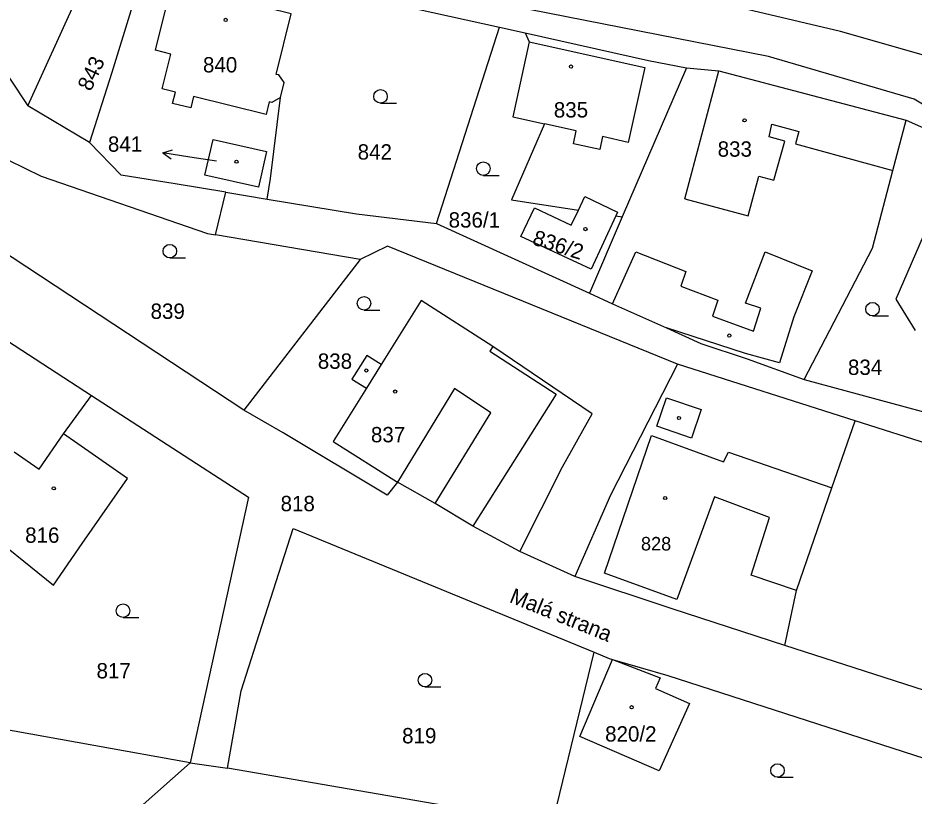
# Model space of a CAD drawing. Extents: x -504988 to -494607, y -1123820 to -1114018.
# Drawn here: x -497288.4 to -497189.2, y -1120348.7 to -1120262.5 of the extents above; entities that cross this region are included whole.
import ezdxf

# ---------------------------------------------------------------- set-up
doc = ezdxf.new("R2010")
doc.units = 0
for name, color, linetype in [('Hranice parcel', 7, 'Continuous'), ('Parcelní čísla', 7, 'Continuous'), ('Pop  PČ popisy', 7, 'Continuous'), ('Vnitřní kresba', 7, 'Continuous'), ('Značky budov', 7, 'Continuous'), ('Značky kultur', 7, 'Continuous')]:
    doc.layers.add(name, color=color, linetype=linetype)

msp = doc.modelspace()

# ---------------------------------------------------------------- linework, layer by layer
at = {"layer": 'Hranice parcel'}
for p, q in [((-497287.3, -1120272.28), (-497278.88, -1120253.77)), ((-497268.65, -1120256.06), (-497235.11, -1120263.57)), ((-497242.06, -1120285.3), (-497235.11, -1120263.57)), ((-497235.11, -1120263.57), (-497232.25, -1120264.21)), ((-497214.42, -1120268.07), (-497221.52, -1120284.58)), ((-497214.42, -1120268.07), (-497210.84, -1120268.41)), ((-497210.84, -1120268.41), (-497190.09, -1120273.86)), ((-497280.46, -1120276.35), (-497287.3, -1120272.28)), ((-497191.56, -1120279.46), (-497190.09, -1120273.86)), ((-497190.09, -1120273.86), (-497183.86, -1120276.68)), ((-497265.39, -1120281.85), (-497271, -1120280.93)), ((-497266.52, -1120286.57), (-497265.39, -1120281.85)), ((-497265.39, -1120281.85), (-497260.8, -1120282.61)), ((-497226.37, -1120283.83), (-497225.66, -1120282.33)), ((-497225.66, -1120282.33), (-497222.02, -1120284.08)), ((-497227.18, -1120285.52), (-497226.37, -1120283.83)), ((-497221.52, -1120284.58), (-497225.15, -1120293.04)), ((-497222.21, -1120284.47), (-497224.95, -1120290.36)), ((-497222.02, -1120284.08), (-497222.21, -1120284.47)), ((-497222.21, -1120284.47), (-497221.52, -1120284.58)), ((-497242.06, -1120285.3), (-497225.15, -1120293.04)), ((-497263.4, -1120305.99), (-497292.46, -1120286.83)), ((-497250.53, -1120289.32), (-497266.52, -1120286.57)), ((-497250.53, -1120289.32), (-497263.4, -1120305.99)), ((-497289.56, -1120298.33), (-497280.27, -1120304.35)), ((-497195.73, -1120307.17), (-497215.4, -1120300.88)), ((-497201.39, -1120302.61), (-497187.05, -1120306.47)), ((-497168.17, -1120315.99), (-497195.73, -1120307.17)), ((-497226.75, -1120324.4), (-497232.86, -1120321.63)), ((-497174.9, -1120341.31), (-497203.53, -1120332.06)), ((-497229.23, -1120351.83), (-497224.61, -1120332.8)), ((-497269.33, -1120345.06), (-497303.98, -1120338.81)), ((-497269.33, -1120345.06), (-497265.2, -1120345.62)), ((-497229.23, -1120351.83), (-497265.2, -1120345.62))]:
    msp.add_line(p, q, dxfattribs=at)
for points in [[(-497087.04, -1120354.48), (-497099.88, -1120329.46), (-497105.48, -1120320.32), (-497114.23, -1120310.57), (-497171.4, -1120273.63), (-497183.51, -1120268.01), (-497197.35, -1120264.04), (-497268.56, -1120247.23), (-497277.08, -1120243.87), (-497341.22, -1120209.24)], [(-497119.99, -1120315.01), (-497135.65, -1120304.45), (-497167.42, -1120284.15), (-497183.16, -1120275.2), (-497189.22, -1120271.56), (-497205.34, -1120266.82), (-497268.46, -1120254.4), (-497279.16, -1120250.56), (-497298.01, -1120244.32), (-497322.64, -1120230.85), (-497340.94, -1120216.65), (-497344.87, -1120214.42)], [(-497319.8, -1120246.25), (-497305.17, -1120245.35), (-497287.3, -1120272.28)], [(-497273.81, -1120254.9), (-497278.02, -1120268.58), (-497280.46, -1120276.35)], [(-497260.8, -1120282.61), (-497260.46, -1120280.35), (-497259.33, -1120271.37), (-497258.92, -1120269.72), (-497259.53, -1120268.87), (-497259.83, -1120268.8), (-497258.16, -1120262.08), (-497266.08, -1120260.12), (-497266.19, -1120260.59), (-497269.85, -1120259.82), (-497268.95, -1120256.58), (-497268.65, -1120256.06)], [(-497232.25, -1120264.21), (-497231.8, -1120265.2), (-497233.64, -1120273.5), (-497230.13, -1120274.28), (-497233.77, -1120282.69), (-497226.37, -1120283.83)], [(-497232.25, -1120264.21), (-497218.59, -1120267.27), (-497214.42, -1120268.07)], [(-497271, -1120280.93), (-497276.97, -1120279.95), (-497280.46, -1120276.35)], [(-497260.87, -1120277.35), (-497261.77, -1120281.31), (-497267.7, -1120279.97), (-497266.8, -1120276.01), (-497260.87, -1120277.35)], [(-497183.86, -1120276.68), (-497191.22, -1120293.71), (-497189.11, -1120297.17)], [(-497289.43, -1120278.3), (-497285.81, -1120280.06), (-497267.4, -1120286.42), (-497266.52, -1120286.57)], [(-497201.39, -1120302.61), (-497193.82, -1120288.05), (-497191.56, -1120279.46)], [(-497260.8, -1120282.61), (-497250.93, -1120284.24), (-497242.06, -1120285.3)], [(-497224.95, -1120290.36), (-497232.74, -1120286.74), (-497231.24, -1120283.59), (-497227.18, -1120285.52)], [(-497215.4, -1120300.88), (-497247.49, -1120287.81), (-497250.53, -1120289.32)], [(-497225.15, -1120293.04), (-497222.58, -1120294.2), (-497216.63, -1120296.87), (-497212.8, -1120298.59), (-497207.68, -1120300.3), (-497201.39, -1120302.61)], [(-497232.86, -1120321.63), (-497228.14, -1120312.28), (-497224.83, -1120306.41), (-497235.84, -1120298.93), (-497243.75, -1120293.83), (-497248.18, -1120300.93), (-497249.79, -1120299.93), (-497251.45, -1120302.55), (-497249.83, -1120303.57), (-497253.5, -1120309.46), (-497246.39, -1120313.96)], [(-497289.56, -1120298.33), (-497297.06, -1120307.17), (-497301.1, -1120311.93), (-497284.46, -1120325.37), (-497281.28, -1120320.75), (-497276.27, -1120313.54), (-497283.36, -1120308.62), (-497280.27, -1120304.35)], [(-497215.4, -1120300.88), (-497222.82, -1120315.39), (-497226.75, -1120324.4)], [(-497280.27, -1120304.35), (-497262.86, -1120315.61), (-497269.33, -1120345.06)], [(-497246.39, -1120313.96), (-497247.52, -1120315.42), (-497259.03, -1120308.51), (-497263.4, -1120305.99)], [(-497203.53, -1120332.06), (-497202.24, -1120325.98), (-497198.3, -1120314.61), (-497195.73, -1120307.17)], [(-497232.86, -1120321.63), (-497238.05, -1120318.82), (-497242.22, -1120316.34), (-497246.39, -1120313.96)], [(-497265.2, -1120345.62), (-497263.69, -1120337.09), (-497261.98, -1120331.77), (-497257.92, -1120319.1), (-497224.61, -1120332.8)], [(-497203.53, -1120332.06), (-497216, -1120328), (-497226.75, -1120324.4)], [(-497224.61, -1120332.8), (-497222.96, -1120333.48), (-497222.6, -1120333.59), (-497216.48, -1120335.38)], [(-497226.21, -1120342.14), (-497222.6, -1120333.59), (-497217.33, -1120335.63)], [(-497216.48, -1120335.38), (-497186.89, -1120344.92), (-497172.95, -1120349.77)], [(-497217.33, -1120335.63), (-497217.83, -1120336.8), (-497214.08, -1120338.48), (-497217.41, -1120345.95), (-497226.21, -1120342.14)], [(-497269.33, -1120345.06), (-497326.71, -1120395.92), (-497336.86, -1120391.96)]]:
    msp.add_lwpolyline(points, dxfattribs=at)
at = {"layer": 'Pop  PČ popisy'}
for p, q in [((-497272.344, -1120277.491), (-497271.277, -1120277.153)), ((-497269.38, -1120277.96), (-497272.344, -1120277.491)), ((-497272.344, -1120277.491), (-497271.433, -1120278.142)), ((-497266.42, -1120278.43), (-497269.38, -1120277.96))]:
    msp.add_line(p, q, dxfattribs=at)
at = {"layer": 'Vnitřní kresba'}
for p, q in [((-497273.18, -1120266.12), (-497272, -1120261.36)), ((-497231.8, -1120265.2), (-497219.02, -1120268.03)), ((-497271.47, -1120266.55), (-497273.18, -1120266.12)), ((-497272.42, -1120270.4), (-497271.47, -1120266.55)), ((-497219.02, -1120268.03), (-497220.86, -1120276.33)), ((-497214.57, -1120282.59), (-497210.84, -1120268.41)), ((-497270.96, -1120270.76), (-497272.42, -1120270.4)), ((-497271.27, -1120272.01), (-497270.96, -1120270.76)), ((-497268.96, -1120271.25), (-497269.27, -1120272.51)), ((-497260.93, -1120273.24), (-497268.96, -1120271.25)), ((-497260.58, -1120271.84), (-497260.93, -1120273.24)), ((-497260.29, -1120271.92), (-497260.58, -1120271.84)), ((-497259.33, -1120271.37), (-497260.29, -1120271.92)), ((-497269.27, -1120272.51), (-497271.27, -1120272.01)), ((-497226.6, -1120275.06), (-497230.13, -1120274.28)), ((-497205.27, -1120275.72), (-497204.94, -1120274.31)), ((-497204.94, -1120274.31), (-497201.96, -1120275.14)), ((-497226.92, -1120276.49), (-497226.6, -1120275.06)), ((-497223.69, -1120275.7), (-497224.01, -1120277.14)), ((-497220.86, -1120276.33), (-497223.69, -1120275.7)), ((-497203.52, -1120276.21), (-497205.27, -1120275.72)), ((-497201.96, -1120275.14), (-497202.33, -1120276.48)), ((-497224.01, -1120277.14), (-497226.92, -1120276.49)), ((-497204.73, -1120280.53), (-497203.52, -1120276.21)), ((-497202.33, -1120276.48), (-497191.56, -1120279.46)), ((-497207.58, -1120284.45), (-497206.41, -1120280.06)), ((-497206.41, -1120280.06), (-497204.73, -1120280.53)), ((-497214.57, -1120282.59), (-497207.58, -1120284.45)), ((-497222.58, -1120294.2), (-497220.01, -1120288.44)), ((-497220.01, -1120288.44), (-497214.49, -1120290.63)), ((-497207.86, -1120294.14), (-497205.71, -1120288.46)), ((-497205.71, -1120288.46), (-497200.51, -1120290.56)), ((-497214.49, -1120290.63), (-497215.04, -1120292.25)), ((-497200.51, -1120290.56), (-497202.51, -1120295.66)), ((-497215.04, -1120292.25), (-497210.95, -1120293.8)), ((-497210.95, -1120293.8), (-497211.54, -1120295.57)), ((-497206.19, -1120294.68), (-497207.86, -1120294.14)), ((-497207, -1120297.24), (-497206.19, -1120294.68)), ((-497211.54, -1120295.57), (-497207, -1120297.24)), ((-497202.51, -1120295.66), (-497204.11, -1120300.73)), ((-497207.86, -1120299.73), (-497216.63, -1120296.87)), ((-497235.84, -1120298.93), (-497236.18, -1120299.46)), ((-497236.18, -1120299.46), (-497228.81, -1120304.21)), ((-497204.11, -1120300.73), (-497207.86, -1120299.73)), ((-497248.18, -1120300.93), (-497249.83, -1120303.57)), ((-497240.07, -1120303.58), (-497246.39, -1120313.96)), ((-497236.07, -1120306.27), (-497240.07, -1120303.58)), ((-497228.81, -1120304.21), (-497238.05, -1120318.82)), ((-497217.69, -1120307.78), (-497216.6, -1120304.62)), ((-497216.6, -1120304.62), (-497212.77, -1120305.93)), ((-497242.22, -1120316.34), (-497236.07, -1120306.27)), ((-497212.77, -1120305.93), (-497213.86, -1120309.1)), ((-497286.06, -1120312.51), (-497283.36, -1120308.62)), ((-497213.86, -1120309.1), (-497217.69, -1120307.78)), ((-497223.48, -1120324.03), (-497218.28, -1120308.81)), ((-497218.28, -1120308.81), (-497210.29, -1120311.72)), ((-497288.82, -1120310.6), (-497286.06, -1120312.51)), ((-497210.29, -1120311.72), (-497209.74, -1120310.65)), ((-497209.74, -1120310.65), (-497198.3, -1120314.61)), ((-497211.31, -1120315.6), (-497215.47, -1120326.96)), ((-497205.21, -1120317.88), (-497211.31, -1120315.6)), ((-497207.26, -1120324.28), (-497205.21, -1120317.88)), ((-497215.47, -1120326.96), (-497223.48, -1120324.03)), ((-497202.24, -1120325.98), (-497207.26, -1120324.28))]:
    msp.add_line(p, q, dxfattribs=at)
at = {"layer": 'Značky budov'}
for centre in [(-497265.397, -1120262.769), (-497227.177, -1120267.939), (-497207.977, -1120273.899), (-497264.207, -1120278.479), (-497225.587, -1120285.939), (-497209.667, -1120297.729), (-497249.837, -1120301.599), (-497246.647, -1120303.929), (-497215.237, -1120306.849), (-497284.427, -1120314.649), (-497216.767, -1120315.719), (-497220.477, -1120338.889)]:
    msp.add_circle(centre, 0.175, dxfattribs=at)
at = {"layer": 'Značky kultur'}
for p, q in [((-497248.263, -1120271.99), (-497246.513, -1120271.99)), ((-497236.893, -1120279.99), (-497235.143, -1120279.99)), ((-497271.583, -1120289.13), (-497269.833, -1120289.13)), ((-497250.093, -1120294.91), (-497248.343, -1120294.91)), ((-497193.813, -1120295.55), (-497192.063, -1120295.55)), ((-497276.763, -1120328.95), (-497275.013, -1120328.95)), ((-497243.343, -1120336.64), (-497241.593, -1120336.64)), ((-497204.333, -1120346.65), (-497202.583, -1120346.65))]:
    msp.add_line(p, q, dxfattribs=at)
for centre in [(-497248.263, -1120271.24), (-497236.893, -1120279.24), (-497271.583, -1120288.38), (-497250.093, -1120294.16), (-497193.813, -1120294.8), (-497276.763, -1120328.2), (-497243.343, -1120335.89), (-497204.333, -1120345.9)]:
    msp.add_circle(centre, 0.75, dxfattribs=at)

# ---------------------------------------------------------------- texts
at = {"layer": 'Parcelní čísla'}
for s, rotation, p in [('843', 65, (-497280.332, -1120270.766)), ('836/2', 342, (-497231.559, -1120287.609))]:
    msp.add_text(s, height=1.7, rotation=rotation, dxfattribs=at).set_placement(p)
for s, height, p in [('840', 1.7, (-497267.915, -1120268.59)), ('835', 1.7, (-497229.085, -1120273.58)), ('841', 1.7, (-497278.435, -1120277.37)), ('842', 1.7, (-497250.795, -1120278.24)), ('833', 1.7, (-497210.955, -1120277.92)), ('836/1', 1.7, (-497240.728, -1120285.77)), ('839', 1.7, (-497273.715, -1120295.88)), ('838', 1.7, (-497255.205, -1120301.41)), ('834', 1.7, (-497196.535, -1120302.09)), ('837', 1.7, (-497249.325, -1120309.55)), ('818', 1.7, (-497259.325, -1120317.18)), ('816', 1.7, (-497287.595, -1120320.68)), ('828', 1.5, (-497219.441, -1120321.53)), ('817', 1.7, (-497279.695, -1120335.7)), ('819', 1.7, (-497245.875, -1120342.89)), ('820/2', 1.7, (-497223.408, -1120342.69))]:
    msp.add_text(s, height=height, dxfattribs=at).set_placement(p)
at = {"layer": 'Pop  PČ popisy'}
msp.add_text('Malá strana', height=1.7, rotation=338, dxfattribs=at).set_placement((-497234.105, -1120327.225))

doc.saveas('drawing.dxf')
